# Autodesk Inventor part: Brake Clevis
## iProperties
Shininess: 70.0
Angle Display Precision: 2
Document Length Units: 11269
Document Angle Units: 11279
Document Time Units: 11290
Document Mass Units: 11283
Document Length Units Precision: 3
Document Angle Units Precision: 2
Compacted: True
Created: 2001-09
Part Number: Brake Clevis
Document SubType Name: Modeling
Designer: Martin Budgell
Density: 0.0
Volumn: 0.0
Area: 0.0
PropertySet Name: Model Information
Control State: 0
Master: False
Checked Out: False
Author: Martin Budgell
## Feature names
1. Extrusion1
2. Extrusion2
3. Hole1
4. Extrusion3
5. Extrusion4
6. Chamfer1
7. Chamfer2
8. Fillet1
9. Revolution1
10. Hole2
11. Chamfer3
12. Fillet2
13. Chamfer4
14. Chamfer5
15. Chamfer6
16. Fillet4
